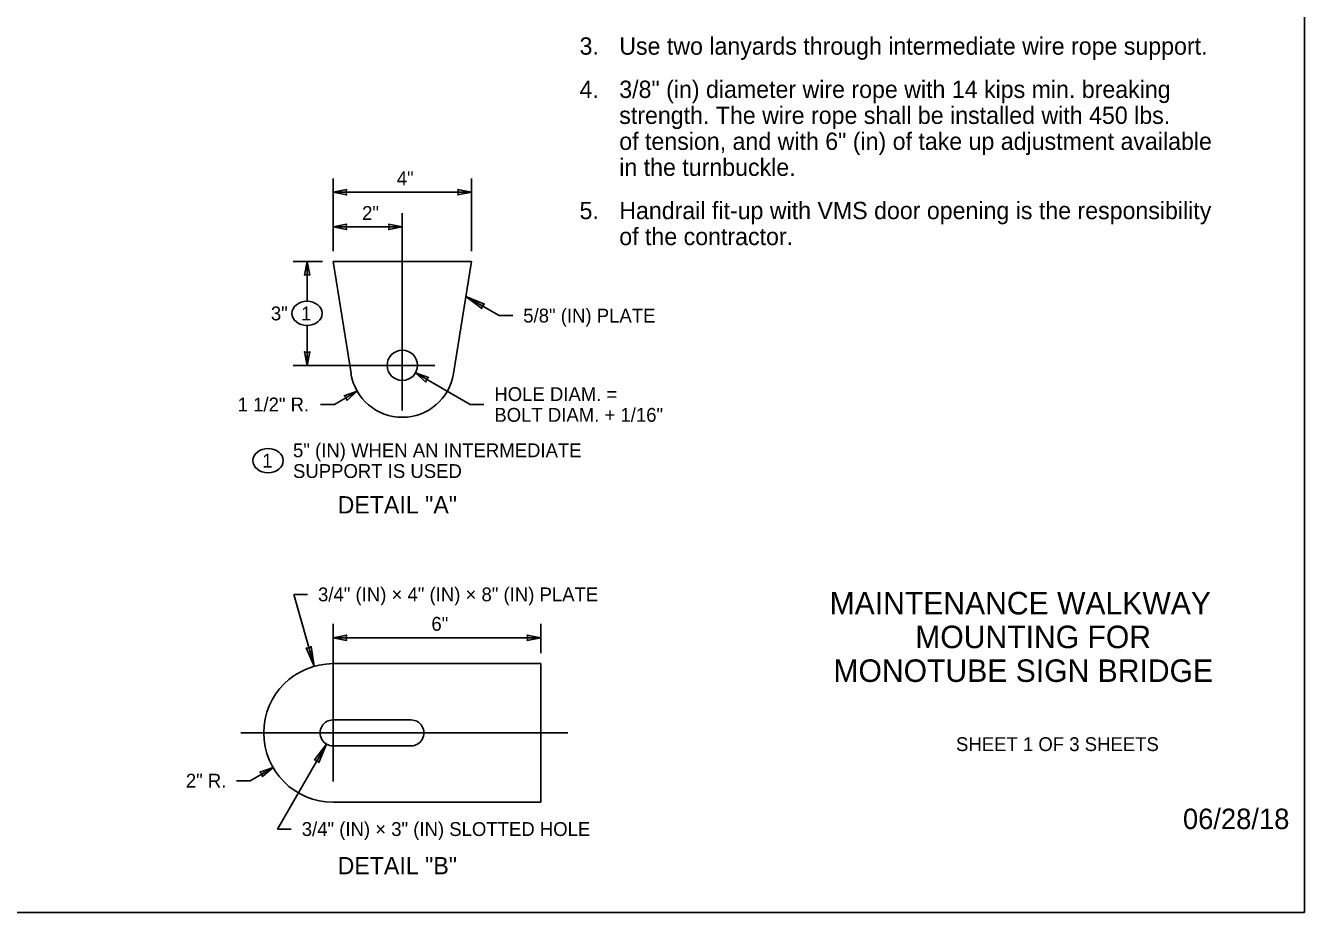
# Model space of a CAD drawing. Extents: x 99862 to 103151, y 100000 to 108076.
# Drawn here: x 101674 to 103151, y 100000 to 101024 of the extents above; entities that cross this region are included whole.
import ezdxf

# ---------------------------------------------------------------- set-up
doc = ezdxf.new("R2010")
doc.units = 0
for name, color, linetype in [('Level 1', 7, 'Continuous'), ('Level 15', 7, 'Continuous'), ('Level 2', 7, 'Continuous'), ('Level 20', 7, 'Continuous'), ('Level 6', 7, 'Continuous'), ('Level 62', 7, 'Continuous')]:
    doc.layers.add(name, color=color, linetype=linetype)

msp = doc.modelspace()

# ---------------------------------------------------------------- linework, layer by layer
at = {"layer": 'Level 1'}
msp.add_lwpolyline([(99862, 99999.5), (103151, 99999.5), (103151, 102075.5), (99862, 102075.5)], close=True, dxfattribs=at)
at = {"layer": 'Level 15'}
for p, q in [((102029.1, 100763.5), (102029.1, 100847.5)), ((102189.1, 100763.5), (102189.1, 100847.5)), ((102189.1, 100831.5), (102029.1, 100831.5)), ((102109.1, 100807.5), (102109.1, 100579.3)), ((102109.1, 100791.5), (102029.1, 100791.5)), ((102017.1, 100751.5), (101983.1, 100751.5)), ((101999.1, 100751.5), (101999.1, 100705.5)), ((102182.6, 100711), (102220.8, 100689)), ((102220.8, 100689), (102236.8, 100689)), ((101999.1, 100677.5), (101999.1, 100631.5)), ((101983.1, 100631.5), (102146.7, 100631.5)), ((102124.2, 100622.8), (102187.4, 100586.3)), ((102057.1, 100601.5), (102030.8, 100586.3)), ((102030.8, 100586.3), (102014.8, 100586.3)), ((102187.4, 100586.3), (102203.4, 100586.3)), ((101983.8, 100366.9), (101999.8, 100366.9)), ((102007.3, 100283.9), (101983.8, 100366.9)), ((102029.1, 100332.9), (102029.1, 100150.9)), ((102269.1, 100298.9), (102269.1, 100332.9)), ((102269.1, 100316.9), (102029.1, 100316.9)), ((102300.2, 100206.9), (101922.8, 100206.9)), ((102021.6, 100193.9), (101964.9, 100095.8)), ((101959.8, 100166.9), (101933.5, 100151.7)), ((101933.5, 100151.7), (101917.5, 100151.7)), ((101964.9, 100095.8), (101980.9, 100095.8))]:
    msp.add_line(p, q, dxfattribs=at)
for points in [[(102029.1, 100831.5), (102044.8, 100828.4), (102044.1, 100831.5), (102044.8, 100834.6)], [(102189.1, 100831.5), (102173.4, 100834.6), (102174.1, 100831.5), (102173.4, 100828.4)], [(102029.1, 100791.5), (102044.8, 100788.4), (102044.1, 100791.5), (102044.8, 100794.6)], [(102109.1, 100791.5), (102093.4, 100794.6), (102094.1, 100791.5), (102093.4, 100788.4)], [(101999.1, 100751.5), (102002.2, 100735.8), (101999.1, 100736.5), (101996, 100735.8)], [(102182.6, 100711), (102203.9, 100702.2), (102201.5, 100700.1), (102200.9, 100697)], [(101999.1, 100631.5), (102002.2, 100647.2), (101999.1, 100646.5), (101996, 100647.2)], [(102124.3, 100622.8), (102136.3, 100612.2), (102137.2, 100615.3), (102139.4, 100617.6)], [(102057.1, 100601.5), (102042, 100596.3), (102044.1, 100594), (102045.1, 100591)], [(102029.1, 100316.9), (102044.8, 100313.8), (102044.1, 100316.9), (102044.8, 100320)], [(102269.1, 100316.9), (102253.4, 100320), (102254.1, 100316.9), (102253.4, 100313.8)], [(102007.3, 100283.9), (102003.9, 100306.7), (102001.4, 100304.8), (101998.2, 100305)], [(102021.6, 100193.9), (102007.6, 100175.6), (102010.7, 100175.1), (102012.8, 100172.7)], [(101959.8, 100166.9), (101944.7, 100161.7), (101946.8, 100159.4), (101947.7, 100156.4)]]:
    msp.add_lwpolyline(points, close=True, dxfattribs=at)
at = {"layer": 'Level 2'}
for p, q in [((102269.1, 100286.9), (102029.1, 100286.9)), ((102269.1, 100286.9), (102269.1, 100126.9)), ((102029.1, 100221.9), (102119.1, 100221.9)), ((102029.1, 100191.9), (102119.1, 100191.9)), ((102269.1, 100126.9), (102029.1, 100126.9))]:
    msp.add_line(p, q, dxfattribs=at)
for centre, radius, start, end in [((102029.1, 100206.9), 80, 90, 270), ((102029.1, 100206.9), 15, 89.9978, 270), ((102119.1, 100206.9), 15, 270, 90.0022)]:
    msp.add_arc(centre, radius, start, end, dxfattribs=at)
at = {"layer": 'Level 20'}
for centre in [(101999.1, 100691.5), (101954.1, 100521.4)]:
    msp.add_ellipse(centre, major_axis=(-17.5, 0), ratio=0.8, dxfattribs=at)
at = {"layer": 'Level 6'}
for p, q in [((102109.1, 100751.5), (102029.1, 100751.5)), ((102049.9, 100622), (102029.1, 100751.5)), ((102189.1, 100751.5), (102109.1, 100751.5)), ((102168.3, 100622), (102189.1, 100751.5))]:
    msp.add_line(p, q, dxfattribs=at)
msp.add_circle((102109.1, 100631.5), 17.5, dxfattribs=at)
for start, end in [(189.1049, 270.0022), (270.0022, 350.8942)]:
    msp.add_arc((102109.1, 100631.5), 60, start, end, dxfattribs=at)

# ---------------------------------------------------------------- texts
at = {"layer": 'Level 15'}
msp.add_text('06/28/18', height=23.62, dxfattribs=at).set_placement((103010.7, 100095.8))
at = {"layer": 'Level 20'}
for s, height, p in [('Use two lanyards through intermediate wire rope support.', 20, (102359.7, 100990.4)), ('3.', 20, (102313.8, 100990.4)), ('4.', 20, (102313.8, 100940.4)), ('3/8" (in) diameter wire rope with 14 kips min. breaking', 20, (102359.7, 100940.4)), ('strength. The wire rope shall be installed with 450 lbs.', 20, (102359.7, 100910.4)), ('of tension, and with 6" (in) of take up adjustment available', 20, (102359.7, 100880.4)), ('in the turnbuckle.', 20, (102359.7, 100850.4)), ('4"', 16, (102102.7, 100839.5)), ('5.', 20, (102313.8, 100800.4)), ('Handrail fit-up with VMS door opening is the responsibility', 20, (102359.7, 100800.4)), ('2"', 16, (102062.7, 100799.5)), ('of the contractor.', 20, (102359.7, 100770.4)), ('3"', 16, (101957.3, 100683.5)), ('1', 16, (101992.2, 100683.5)), ('5/8" (IN) PLATE', 16, (102248.8, 100681)), ('HOLE DIAM. =', 16, (102215.4, 100590.3)), ('1 1/2" R.', 16, (101919, 100578.3)), ('BOLT DIAM. + 1/16"', 16, (102215.4, 100566.3)), ('5" (IN) WHEN AN INTERMEDIATE', 16, (101982.9, 100525.4)), ('1', 16, (101947.3, 100513.4)), ('SUPPORT IS USED', 16, (101982.9, 100501.4)), ('DETAIL "A"', 20, (102034.4, 100460.4)), ('3/4" (IN) × 4" (IN) × 8" (IN) PLATE', 16, (102011.8, 100358.9)), ('6"', 16, (102142.7, 100324.9)), ('2" R.', 16, (101859.1, 100143.7)), ('3/4" (IN) × 3" (IN) SLOTTED HOLE', 16, (101993, 100087.8)), ('DETAIL "B"', 20, (102034.4, 100043.5))]:
    msp.add_text(s, height=height, dxfattribs=at).set_placement(p)
at = {"layer": 'Level 62'}
for s, height, p in [('MAINTENANCE WALKWAY', 26, (102602.6, 100343.8)), ('MOUNTING FOR', 26, (102701.5, 100304.8)), ('MONOTUBE SIGN BRIDGE', 26, (102607, 100265.8)), ('SHEET 1 OF 3 SHEETS', 16, (102748.6, 100185.9))]:
    msp.add_text(s, height=height, dxfattribs=at).set_placement(p)

doc.saveas('drawing.dxf')
